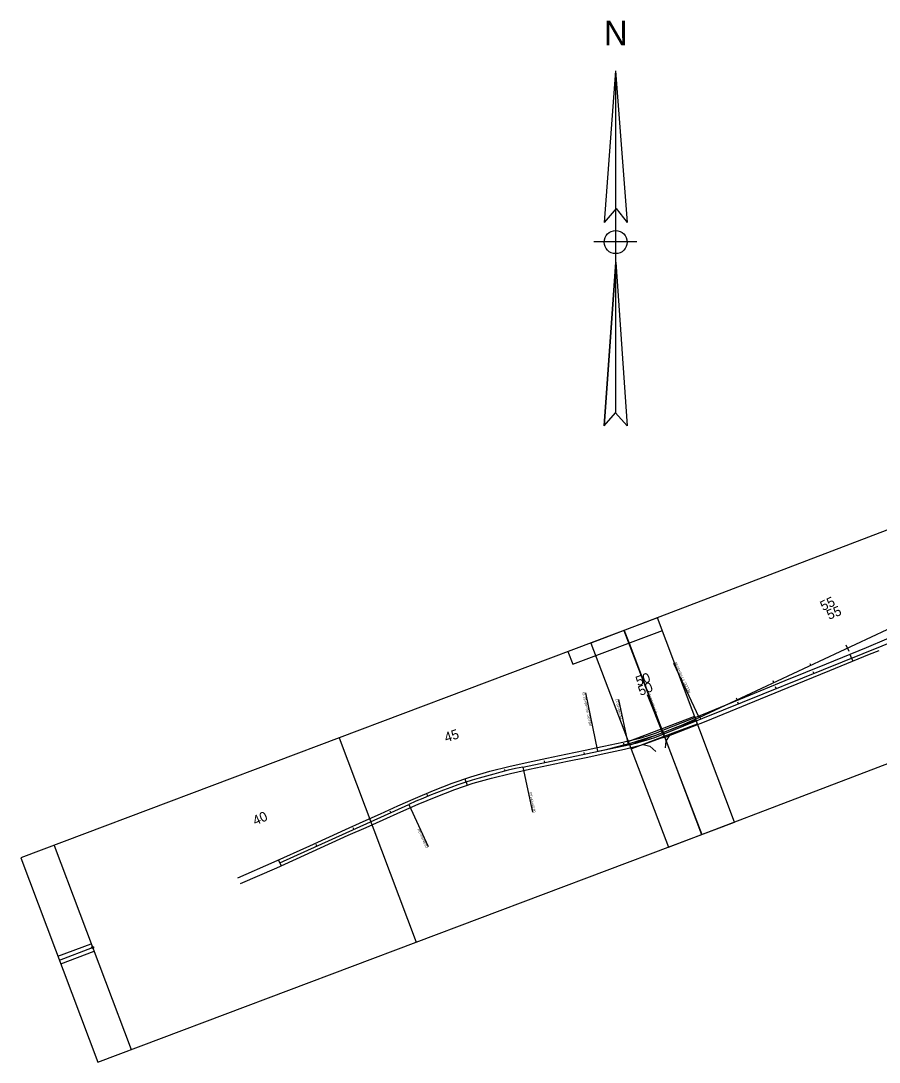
# Model space of a CAD drawing. Extents: x 1965190 to 1971239, y 1116641 to 1119319.
# Drawn here: x 1965190 to 1967302, y 1116641 to 1119204 of the extents above; entities that cross this region are included whole.
import ezdxf

# ---------------------------------------------------------------- set-up
doc = ezdxf.new("R2010")
doc.units = 0
for name, color, linetype in [('RD_EX_Misc', 7, 'Continuous'), ('RD_EX_Road', 7, 'Continuous'), ('RD_HC_Cl', 7, 'Continuous'), ('RD_HC_CL_Rel', 7, 'Continuous'), ('RD_HC_Data', 7, 'Continuous'), ('RD_HC_Data_Rel', 7, 'Continuous'), ('RD_HC_Data_Tic', 7, 'Continuous'), ('RD_HC_Data_Tic_Rel', 7, 'Continuous'), ('RD_HC_TX_Rel_Sta50', 7, 'Continuous'), ('RD_HC_TX_Sta50', 7, 'Continuous'), ('RD_SHT_Bndy', 7, 'Continuous'), ('RD_SHT_Misc3', 7, 'Continuous')]:
    doc.layers.add(name, color=color, linetype=linetype)

msp = doc.modelspace()

# ---------------------------------------------------------------- linework, layer by layer
at = {"layer": 'RD_EX_Misc'}
for p, q in [((1966653.2, 1119081.1), (1966625.4, 1118707.9)), ((1966653.2, 1119081.1), (1966682.2, 1118707.9)), ((1966653.2, 1119081.1), (1966653.2, 1118238.3)), ((1966654.6, 1118742.1), (1966625.4, 1118707.9)), ((1966654.6, 1118742.1), (1966682.2, 1118707.9)), ((1966600.2, 1118660.7), (1966705.8, 1118660.7)), ((1966654, 1118610.3), (1966625.6, 1118206.9)), ((1966625.6, 1118206.9), (1966654, 1118610.3)), ((1966654, 1118610.3), (1966681.6, 1118206.9)), ((1966625.6, 1118206.9), (1966653.4, 1118239.1)), ((1966681.6, 1118206.9), (1966653.4, 1118239.1))]:
    msp.add_line(p, q, dxfattribs=at)
msp.add_circle((1966653.6, 1118659.5), 28.4, dxfattribs=at)
at = {"layer": 'RD_EX_Road'}
for points in [[(1966769.5, 1117457.5), (1966870.2, 1117497.3), (1966971.2, 1117539), (1967071.1, 1117580.2), (1967172.6, 1117621.5), (1967270.8, 1117661.7), (1967321.1, 1117682.6), (1967371.5, 1117702.9), (1967470.3, 1117741.6), (1967566.7, 1117779.5), (1967661.2, 1117817.5), (1967694.4, 1117831.2), (1967697.9, 1117822.8)], [(1966775.8, 1117440.6), (1966876.2, 1117480.4), (1966978.5, 1117522.1), (1967078.3, 1117563.1), (1967180.7, 1117605.1), (1967278, 1117644.7), (1967302.2, 1117654.1)], [(1965723.8, 1117094.5), (1965813.3, 1117133.7), (1965900.5, 1117173.5), (1965988.5, 1117213.4), (1966031.8, 1117233), (1966074.7, 1117252.1), (1966117.8, 1117271.6), (1966161.1, 1117290.5), (1966205.4, 1117309.2), (1966251.2, 1117327.4), (1966297.2, 1117343.1), (1966344.1, 1117357), (1966390.8, 1117368.6), (1966438.1, 1117379.1), (1966484.5, 1117389.1), (1966531.2, 1117398.7), (1966578.4, 1117408.6), (1966604.5, 1117414.1), (1966624.5, 1117418.3), (1966671.3, 1117428.3), (1966716.5, 1117439.3), (1966736.6, 1117445.6), (1966754.1, 1117451.4), (1966759.7, 1117453.5), (1966769.5, 1117457.5)], [(1965730, 1117080.3), (1965819.8, 1117119.1), (1965907.7, 1117159.3), (1965995.4, 1117199), (1966039.3, 1117218.5), (1966081.2, 1117237.1), (1966124.7, 1117256.6), (1966167.7, 1117275.6), (1966211.5, 1117293.6), (1966257.8, 1117311.6), (1966302.7, 1117327.2), (1966347.9, 1117340), (1966394.8, 1117351.6), (1966441.6, 1117361.9), (1966488.6, 1117372.1), (1966534.9, 1117381.3), (1966581.2, 1117390.9), (1966629.5, 1117400.9), (1966675.6, 1117411.1), (1966721.7, 1117422.8), (1966766.8, 1117439), (1966775.8, 1117440.6)], [(1966776.2, 1117414.3), (1966777.9, 1117430.8), (1966787.3, 1117445.2)], [(1966721.5, 1117422.8), (1966737.9, 1117418.6), (1966752.2, 1117405.6)]]:
    msp.add_lwpolyline(points, dxfattribs=at)
at = {"layer": 'RD_HC_Cl'}
for p, q in [((1966770.7, 1117448.1), (1967849.5, 1117883.9)), ((1966425.3, 1117367.2), (1966684.9, 1117421.9)), ((1965826.9, 1117131.2), (1966144.7, 1117275.3))]:
    msp.add_line(p, q, dxfattribs=at)
for centre, radius, start, end in [((1966579.6, 1117921.3), 510.3, 281.9047, 291.9958), ((1966705.5, 1116038), 1358.4, 101.9047, 114.3826)]:
    msp.add_arc(centre, radius, start, end, dxfattribs=at)
at = {"layer": 'RD_HC_CL_Rel'}
msp.add_line((1966858.9, 1117489.3), (1967685.7, 1117875.7), dxfattribs=at)
msp.add_arc((1966373.7, 1118527.5), 1145.9, 281.9047, 295.0463, dxfattribs=at)
at = {"layer": 'RD_HC_Data'}
for p, q in [((1966684.9, 1117421.9), (1966661.4, 1117533.5)), ((1966770.7, 1117448.1), (1966731.7, 1117544.7)), ((1966425.3, 1117367.2), (1966448.7, 1117256.1)), ((1966144.7, 1117275.3), (1966191.8, 1117171.4))]:
    msp.add_line(p, q, dxfattribs=at)
at = {"layer": 'RD_HC_Data_Rel'}
for p, q in [((1966858.9, 1117489.3), (1966796.7, 1117622.3)), ((1966610.1, 1117406.2), (1966579.8, 1117550))]:
    msp.add_line(p, q, dxfattribs=at)
at = {"layer": 'RD_HC_Data_Tic'}
for p, q in [((1967234.3, 1117635.4), (1967231.3, 1117642.8)), ((1967234.3, 1117635.4), (1967237.3, 1117628)), ((1967141.6, 1117597.9), (1967140.1, 1117601.6)), ((1967048.9, 1117560.5), (1967047.4, 1117564.2)), ((1966956.2, 1117523), (1966954.7, 1117526.7)), ((1966863.5, 1117485.6), (1966862, 1117489.3)), ((1966770.7, 1117448.1), (1966767.7, 1117455.5)), ((1966770.7, 1117448.1), (1966773.7, 1117440.7)), ((1966577.1, 1117399.2), (1966576.3, 1117403.1)), ((1966675, 1117419.9), (1966674.1, 1117423.8)), ((1966479.3, 1117378.6), (1966478.4, 1117382.5)), ((1966381.6, 1117357.3), (1966380.6, 1117361.1)), ((1966285.4, 1117329.9), (1966283, 1117337.5)), ((1966285.4, 1117329.9), (1966287.9, 1117322.2)), ((1966191.6, 1117295.5), (1966190, 1117299.2)), ((1966100.1, 1117255.1), (1966098.4, 1117258.7)), ((1966009, 1117213.8), (1966007.4, 1117217.4)), ((1965917.9, 1117172.5), (1965916.3, 1117176.1)), ((1965826.9, 1117131.2), (1965823.5, 1117138.5)), ((1965826.9, 1117131.2), (1965830.2, 1117123.9))]:
    msp.add_line(p, q, dxfattribs=at)
at = {"layer": 'RD_HC_Data_Tic_Rel'}
for p, q in [((1967224.4, 1117660.1), (1967221, 1117667.3)), ((1967224.4, 1117660.1), (1967227.8, 1117652.8)), ((1967133.8, 1117617.8), (1967132.1, 1117621.4)), ((1967043.2, 1117575.4), (1967041.5, 1117579)), ((1966952.6, 1117533.1), (1966950.9, 1117536.7)), ((1966862, 1117490.8), (1966860.3, 1117494.4)), ((1966769.8, 1117452.2), (1966767, 1117459.7)), ((1966769.8, 1117452.2), (1966772.5, 1117444.6)), ((1966674.5, 1117421.7), (1966673.5, 1117425.6))]:
    msp.add_line(p, q, dxfattribs=at)
at = {"layer": 'RD_SHT_Bndy'}
for p, q in [((1966673.9, 1117703.2), (1966865.7, 1117201.1)), ((1966686.6, 1117672.5), (1966864.6, 1117200.7)), ((1966766.2, 1117461.5), (1966848.1, 1117492.4)), ((1966684.5, 1117430.3), (1966766.2, 1117461.5)), ((1966773.3, 1117442.8), (1966855.2, 1117473.7)), ((1966691.6, 1117411.6), (1966773.3, 1117442.8)), ((1965271.4, 1117174.3), (1965461.1, 1116671.4)), ((1965280.9, 1116901.3), (1965362.7, 1116932.2)), ((1965287.9, 1116882.6), (1965369.8, 1116913.5))]:
    msp.add_line(p, q, dxfattribs=at)
for points in [[(1966783.9, 1117169.9), (1968348.7, 1117767.5), (1968156.9, 1118269.6), (1966592.1, 1117672)], [(1965379.2, 1116640.5), (1966946.5, 1117231.6), (1966756.8, 1117734.5), (1965189.6, 1117143.4)]]:
    msp.add_lwpolyline(points, close=True, dxfattribs=at)
msp.add_lwpolyline([(1966536.1, 1117651.3), (1966547.8, 1117620.2), (1966768.5, 1117703.4)], dxfattribs=at)
at = {"layer": 'RD_SHT_Misc3'}
for p, q in [((1966674.9, 1117703.6), (1966686.6, 1117672.5)), ((1966769.8, 1117452.2), (1966851.6, 1117483)), ((1965973.2, 1117439), (1966162.8, 1116936)), ((1966688, 1117420.9), (1966769.8, 1117452.2)), ((1965284.4, 1116892), (1965366.3, 1116922.8))]:
    msp.add_line(p, q, dxfattribs=at)
for centre in [(1966769.8, 1117452.2), (1966769.8, 1117452.2), (1965366.3, 1116922.8)]:
    msp.add_circle(centre, 2.5, dxfattribs=at)

# ---------------------------------------------------------------- texts
at = {"layer": 'RD_EX_Misc'}
msp.add_text('N', height=60, dxfattribs=at).set_placement((1966624.9, 1119144.3))
at = {"layer": 'RD_HC_Data'}
for s, rotation, p in [('PC=49+10.12', 101.9047, (1966669.5, 1117485.1)), ('PT=50+00.00', 111.9958, (1966756.6, 1117502)), ('PT=46+44.80', 281.9047, (1966440.6, 1117304)), ('PC=43+48.97', 294.3826, (1966165.3, 1117213.3))]:
    msp.add_text(s, height=6, rotation=rotation, dxfattribs=at).set_placement(p)
at = {"layer": 'RD_HC_Data_Rel'}
for s, rotation, p in [('RELOC. PT=50+96.56', 115.0463, (1966838.3, 1117551)), ('RELOC. PC=48+33.73', 101.9047, (1966594.8, 1117469.4))]:
    msp.add_text(s, height=6, rotation=rotation, dxfattribs=at).set_placement(p)
at = {"layer": 'RD_HC_TX_Rel_Sta50'}
for s, rotation, p in [('55', 25.0463, (1967163.8, 1117751)), ('50', 20.2184, (1966708.1, 1117565.7))]:
    msp.add_text(s, height=24, rotation=rotation, dxfattribs=at).set_placement(p)
at = {"layer": 'RD_HC_TX_Sta50'}
for s, rotation, p in [('55', 21.9958, (1967178.7, 1117729.4)), ('50', 21.9958, (1966714.6, 1117541.9)), ('45', 18.0122, (1966236.4, 1117427.5)), ('40', 24.3826, (1965766.9, 1117222.6))]:
    msp.add_text(s, height=24, rotation=rotation, dxfattribs=at).set_placement(p)

doc.saveas('drawing.dxf')
